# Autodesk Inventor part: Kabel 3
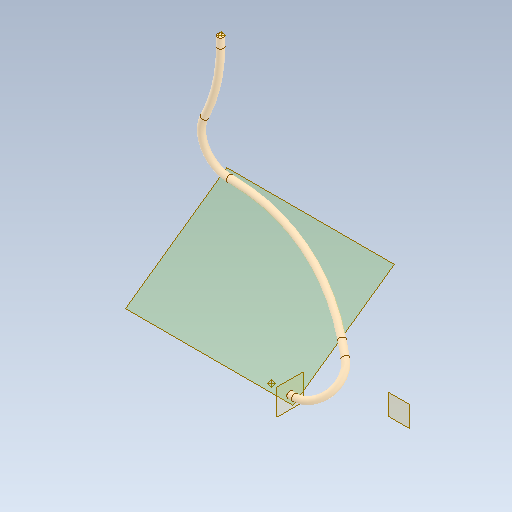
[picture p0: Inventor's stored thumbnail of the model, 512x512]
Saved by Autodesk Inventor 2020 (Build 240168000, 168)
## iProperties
Created: 2025-04
Part Number: Kabel 3
Material: Polyetylen, S vysokou hustotou
Document SubType Name: Modeling
Designer: doma
Density: 0.952 g/cm^3
Appearance: Hladká – špinavě bílá
Author: doma
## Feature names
1. Tažení1
## Parameters: d1 = 5 mm, d2 = 7 mm, d3 = 0, d4 = 0
